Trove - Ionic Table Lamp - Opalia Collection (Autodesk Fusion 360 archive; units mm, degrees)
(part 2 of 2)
create_component "CreateComponent4"
create_component "CreateComponent5"
create_component "CreateComponent6"
create_component "CreateComponent7"
create_component "CreateComponent8"
remove_body "RemoveBody1"
create_component "CreateComponent9"
create_component "CreateComponent10"
create_component "CreateComponent11"
create_component "CreateComponent12"
create_component "CreateComponent13"
create_component "CreateComponent14"
create_component "CreateComponent15"
create_component "CreateComponent16"
create_component "CreateComponent17"
create_component "CreateComponent18"
remove_body "RemoveBody6"
create_component "CreateComponent19"
create_component "CreateComponent20"
create_component "CreateComponent21"
create_component "CreateComponent22"
create_component "CreateComponent23"
named bodies: "Marble Base", "Rotary Switch", "Coiled - SVT (Blk Fabric)", "Glass Globe", "Metal Housing", "Metal Socket Cover", "Porcelain Socket", "Brass Dial - Dimmer Knob", "Solitaire Petite", "Facet Petite", "Body1", "Body2", "Plastic Insert", "Silicone Gasket", "Oculo Petite", "Balon v2", "Balon v3", "Trove - TL", "Trove - TL (1)", "Neoprene Pad", "2-Pole Plug End", "Rubber Grommet", "Chinois"

design "Trove - TL"
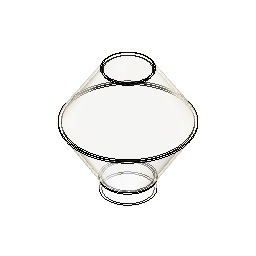
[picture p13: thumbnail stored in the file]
derived_base_feature "Derived Base Feature" bodies "Trove"
hole "Hole1" HoleDepth 88.9 HoleDiameter 44.45 TipAngle 118
sketch "Sketch1" plane through (0, 0, 0) normal (1, 0, 0) x axis (0, 1, 0)
  line L1 (0, 243.0601) -> (0, 247.8226)
  line L2 (-50.8, -12.7122) -> (-50.8, 10.9447)
  line L3 (0, -25.4) -> (0, 243.0601)
  line L4 (-46.0375, -12.7122) -> (-50.8, -12.7122)
  line L5 (-46.0375, -12.7122) -> (-46.0375, 12.3043)
  line L6 (-45.9716, 247.8226) -> (0, 247.8226)
  line L7 (-43.3841, 243.0601) -> (0, 243.0601)
  line L8 (-122.8321, 128.6352) -> (-51.757, 14.2971)
  line L9 (-117.1907, 128.5808) -> (-46.9945, 15.6567)
  line L10 (-48.6353, 246.3754) -> (-122.7993, 132.0392)
  line L11 (-46.0478, 241.6129) -> (-117.1579, 131.9848)
  arc A1 centre (-57.15, 10.9447) radius 6.35 clockwise from (-51.757, 14.2971) to (-50.8, 10.9447)
  arc A2 centre (-52.3875, 12.3043) radius 6.35 clockwise from (-46.9945, 15.6567) to (-46.0375, 12.3043)
  arc A3 centre (-114.4942, 130.257) radius 3.175 between (-117.1579, 131.9848) and (-117.1907, 128.5808)
  arc A4 centre (-120.1356, 130.3114) radius 3.175 between (-122.7993, 132.0392) and (-122.8321, 128.6352)
  arc A5 centre (-45.9716, 244.6476) radius 3.175 between (-45.9716, 247.8226) and (-48.6353, 246.3754)
  arc A6 centre (-43.3841, 239.8851) radius 3.175 clockwise from (-46.0478, 241.6129) to (-43.3841, 243.0601)
  point P3 (0, 247.8226)
  point P4 (0, 243.0601)
  vertical L1
  vertical L3
  tangent L5 A2
  perpendicular L1 L6
  perpendicular L1 L7
  tangent L11 A3
  tangent L9 A3
  tangent L10 A4
  tangent L8 A4
  equal A3 A4
  tangent L6 A5
  tangent L10 A5
  tangent L11 A6
  tangent L7 A6
  dimension "d8" distance P3 P4 = 4.7625
  dimension "d11" radius A2 = 6.35
  dimension "d15" radius A3 = 3.175
  dimension "d16" radius A5 = 3.175
  dimension "d17" radius A6 = 3.175
revolve "Revolve1" sketch "Sketch1" AlongAngle 180 bodies "Trove - TL"
revolve "Revolve2" sketch "Sketch1" AlongAngle -180
component_from_bodies "Body->Comp"
remove_body "RemoveBody2"
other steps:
base_feature "Base Feature" bodies "Trove - TL"
create_component "CreateComponent1"
remove_body "RemoveBody1"
named bodies: "Trove", "Trove - TL"

design "T9-5In"
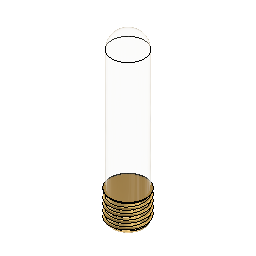
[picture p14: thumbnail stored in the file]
sketch "Sketch1" plane through (0, 0, 0) normal (0, 1, 0) x axis (1, 0, 0)
  line L1 (0, 0) -> (0, -127)
  line L2 (12.7, -127) -> (-12.7, -127)
  line L3 (12.7, -12.7) -> (12.7, -127)
  line L4 (-12.7, -127) -> (-12.7, -12.7)
  arc A1 centre (0, -12.7) radius 12.7 clockwise from (-12.7, -12.7) to (12.7, -12.7)
  point P1 (0, 0)
  point P3 (0, 0)
  coincident P1 P3
  vertical L1
  horizontal L2
  vertical L3
  vertical L4
revolve "Revolve1" sketch "Sketch1" AlongAngle 360 bodies "BU-T10-5-LED-120V"
derived_base_feature "Derived Base Feature" bodies "E26 Base"
move "Move1"
component_from_bodies "Body->Comp"
copy_paste "CutPaste"
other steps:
base_feature "Base Feature" bodies "BU-T10-5-LED-120V"
create_component "CreateComponent1"
create_component "CreateComponent2"
remove_body "RemoveBody1"
remove_instance "RemoveInstance1"
named bodies: "BU-T10-5-LED-120V", "E26 Base"

design "Balon v2"
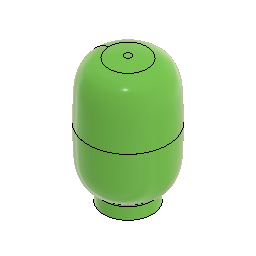
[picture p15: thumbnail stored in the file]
derived_base_feature "Derived Base Feature" bodies "Balon"
work_plane "WorkPlane1" AlongDistance 0
sketch "Sketch1" plane through (0, 0, 0) normal (0, 1, 0) x axis (1, 0, 0)
  line L1 (0, 317.5) -> (0, 2.9083)
  curve K1 (-82.9821, 124.2212) -> (-50.8, 237.8015)
  curve K2 (-51.0925, 237.681) -> (-50.8, 237.8015)
  curve K3 (-51.3855, 237.5558) -> (-51.0925, 237.681)
  curve K4 (-54.7608, 236.0513) -> (-51.3855, 237.5558)
  curve K5 (-57.9615, 234.05) -> (-54.7608, 236.0513)
  curve K6 (-67.2727, 226.749) -> (-57.9615, 234.05)
  curve K7 (-69.0552, 224.2615) -> (-67.2727, 226.749)
  curve K8 (-72.1872, 218.7832) -> (-69.0552, 224.2615)
  curve K9 (-74.1213, 215.1556) -> (-72.1872, 218.7832)
  curve K10 (-78.3031, 204.3965) -> (-74.1213, 215.1556)
  curve K11 (-79.7275, 197.3397) -> (-78.3031, 204.3965)
  curve K12 (-81.3333, 185.4664) -> (-79.7275, 197.3397)
  curve K13 (-81.6254, 178.4008) -> (-81.3333, 185.4664)
  curve K14 (-82.49, 152.2133) -> (-81.6254, 178.4008)
  curve K15 (-82.9821, 136.067) -> (-82.49, 152.2133)
  curve K16 (-82.9821, 124.2212) -> (-82.9821, 136.067)
  curve K17 (50.8, 237.7999) -> (82.9821, 124.2212)
  curve K18 (82.9821, 140.3031) -> (82.9821, 124.2212)
  curve K19 (81.9353, 169.4257) -> (82.9821, 140.3031)
  curve K20 (81.3621, 183.6489) -> (81.9353, 169.4257)
  curve K21 (80.9478, 189.8724) -> (81.3621, 183.6489)
  curve K22 (77.8147, 206.9858) -> (80.9478, 189.8724)
  curve K23 (74.9652, 213.2153) -> (77.8147, 206.9858)
  curve K24 (69.4688, 224.1531) -> (74.9652, 213.2153)
  curve K25 (67.2512, 226.458) -> (69.4688, 224.1531)
  curve K26 (61.5696, 231.3138) -> (67.2512, 226.458)
  curve K27 (57.377, 234.6711) -> (61.5696, 231.3138)
  curve K28 (52.0556, 237.2628) -> (57.377, 234.6711)
  curve K29 (51.4313, 237.5413) -> (52.0556, 237.2628)
  curve K30 (50.8, 237.7999) -> (51.4313, 237.5413)
  line L2 (-50.8, 317.5) -> (-50.8, 237.8015)
  line L3 (50.8, 317.5) -> (50.8, 237.7999)
  line L4 (-19.0713, 6.7501) -> (-19.0713, 6.7501)
  curve K31 (82.9821, 124.1958) -> (40.1509, 7.3012)
  curve K32 (41.8198, 7.6176) -> (40.1509, 7.3012)
  curve K33 (43.2113, 8.0663) -> (41.8198, 7.6176)
  curve K34 (47.0139, 9.2854) -> (43.2113, 8.0663)
  curve K35 (47.3314, 9.3805) -> (47.0139, 9.2854)
  curve K36 (50.1192, 10.3272) -> (47.3314, 9.3805)
  curve K37 (51.833, 11.0085) -> (50.1192, 10.3272)
  curve K38 (57.8313, 14.1895) -> (51.833, 11.0085)
  curve K39 (61.4491, 17.0488) -> (57.8313, 14.1895)
  curve K40 (66.8203, 21.5867) -> (61.4491, 17.0488)
  curve K41 (68.5372, 23.5528) -> (66.8203, 21.5867)
  curve K42 (71.2201, 27.8971) -> (68.5372, 23.5528)
  curve K43 (74.7424, 33.8984) -> (71.2201, 27.8971)
  curve K44 (78.2342, 44.8406) -> (74.7424, 33.8984)
  curve K45 (79.6792, 50.3463) -> (78.2342, 44.8406)
  curve K46 (81.3558, 63.5576) -> (79.6792, 50.3463)
  curve K47 (81.6386, 70.4415) -> (81.3558, 63.5576)
  curve K48 (82.4897, 96.2198) -> (81.6386, 70.4415)
  curve K49 (82.9814, 112.3523) -> (82.4897, 96.2198)
  curve K50 (82.9821, 124.1958) -> (82.9814, 112.3523)
  curve K51 (-40.1501, 7.301) -> (-82.9821, 124.1958)
  curve K52 (-82.9813, 110.5256) -> (-82.9821, 124.1958)
  curve K53 (-82.2545, 88.8594) -> (-82.9813, 110.5256)
  curve K54 (-81.6277, 70.519) -> (-82.2545, 88.8594)
  curve K55 (-81.3572, 64.3441) -> (-81.6277, 70.519)
  curve K56 (-79.4149, 46.8924) -> (-81.3572, 64.3441)
  curve K57 (-76.5204, 38.9768) -> (-79.4149, 46.8924)
  curve K58 (-73.5142, 32.2947) -> (-76.5204, 38.9768)
  curve K59 (-72.5556, 30.3818) -> (-73.5142, 32.2947)
  curve K60 (-69.7914, 25.3691) -> (-72.5556, 30.3818)
  curve K61 (-68.3824, 23.4028) -> (-69.7914, 25.3691)
  curve K62 (-64.5419, 19.5456) -> (-68.3824, 23.4028)
  curve K63 (-62.3002, 17.7646) -> (-64.5419, 19.5456)
  curve K64 (-53.6583, 11.1976) -> (-62.3002, 17.7646)
  curve K65 (-49.6968, 10.1396) -> (-53.6583, 11.1976)
  curve K66 (-43.4141, 8.1331) -> (-49.6968, 10.1396)
  curve K67 (-41.9704, 7.6516) -> (-43.4141, 8.1331)
  curve K68 (-40.1963, 7.3098) -> (-41.9704, 7.6516)
  curve K69 (-40.1732, 7.3054) -> (-40.1963, 7.3098)
  curve K70 (-40.1501, 7.301) -> (-40.1732, 7.3054)
  line L5 (-82.9821, 124.1958) -> (-82.9821, 124.2212)
  line L6 (82.9821, 124.2212) -> (82.9821, 124.1958)
  line L7 (0, 317.5) -> (-50.8, 317.5)
  line L8 (7.2015, 3.048) -> (0, 3.048)
  line L9 (0, 3.048) -> (-7.2015, 3.048)
  arc A1 centre (0, 188.595) radius 185.6867 clockwise from (-7.2015, 3.048) to (-40.1502, 7.301)
  arc A2 centre (0, 188.595) radius 185.6867 clockwise from (40.151, 7.3012) to (7.2015, 3.048)
  point P38 (-40.1502, 7.301)
  point P43 (40.1509, 7.3012)
  point P62 (-40.1501, 7.301)
  point P81 (40.151, 7.3012)
  point P84 (0, 3.048)
  vertical L1
  horizontal L4
  coincident P38 K51
  symmetric L1 A1 A2
  coincident A2 P43
  coincident A1 P62
  coincident K31 P81
  perpendicular L2 L7
  horizontal L8
  coincident L1 P84
  horizontal L9
revolve "Revolve1" sketch "Sketch1" AlongAngle 360
shell "Shell1" innerThickness 3.81
fillet "Fillet1" radius 6.35
offset_faces "OffsetFaces1" distance -50.8
move "Move1"
move "Move2"
component_from_bodies "Body->Comp1"
component_from_bodies "Body->Comp2"
sketch "Sketch2" plane through (0, 0, 0) normal (0, 1, 0) x axis (1, 0, 0)
  line L1 (-85.5221, 124.2212) -> (-85.5221, 124.1961)
  curve K1 (-58.9057, 236.4383) -> (-50.8, 241.7989)
  curve K2 (-50.8, 241.554) -> (-50.8, 241.7989)
  curve K3 (-50.904, 240.933) -> (-50.8, 241.554)
  curve K4 (-51.2936, 240.2837) -> (-50.904, 240.933)
  curve K5 (-51.734, 239.7561) -> (-51.2936, 240.2837)
  curve K6 (-53.328, 238.5038) -> (-51.734, 239.7561)
  curve K7 (-54.0892, 238.1997) -> (-53.328, 238.5038)
  curve K8 (-58.9057, 236.4383) -> (-54.0892, 238.1997)
  curve K9 (-89.3309, 124.2212) -> (-58.9057, 236.4383)
  curve K10 (-62.6336, 234.9735) -> (-58.9057, 236.4383)
  curve K11 (-65.581, 233.1032) -> (-62.6336, 234.9735)
  curve K12 (-73.0224, 227.0019) -> (-65.581, 233.1032)
  curve K13 (-74.8981, 224.836) -> (-73.0224, 227.0019)
  curve K14 (-78.1104, 219.6097) -> (-74.8981, 224.836)
  curve K15 (-80.2663, 215.561) -> (-78.1104, 219.6097)
  curve K16 (-84.0943, 205.8277) -> (-80.2663, 215.561)
  curve K17 (-85.4655, 200.1154) -> (-84.0943, 205.8277)
  curve K18 (-87.4092, 188.5789) -> (-85.4655, 200.1154)
  curve K19 (-87.7349, 182.3889) -> (-87.4092, 188.5789)
  curve K20 (-88.4233, 165.9645) -> (-87.7349, 182.3889)
  curve K21 (-89.328, 138.6964) -> (-88.4233, 165.9645)
  curve K22 (-89.3309, 124.2212) -> (-89.328, 138.6964)
  line L2 (-89.3309, 124.1958) -> (-89.3309, 124.2212)
  curve K23 (-46.5001, 7.301) -> (-89.3309, 124.1958)
  curve K24 (-89.3314, 112.4293) -> (-89.3309, 124.1958)
  curve K25 (-88.8181, 95.3068) -> (-89.3314, 112.4293)
  curve K26 (-88.346, 81.2892) -> (-88.8181, 95.3068)
  curve K27 (-88.0298, 70.4902) -> (-88.346, 81.2892)
  curve K28 (-87.1514, 58.328) -> (-88.0298, 70.4902)
  curve K29 (-86.3326, 50.6119) -> (-87.1514, 58.328)
  curve K30 (-81.0932, 33.6688) -> (-86.3326, 50.6119)
  curve K31 (-77.3163, 27.4309) -> (-81.0932, 33.6688)
  curve K32 (-74.8955, 23.6666) -> (-77.3163, 27.4309)
  curve K33 (-73.5108, 22.0741) -> (-74.8955, 23.6666)
  curve K34 (-70.2346, 19.0457) -> (-73.5108, 22.0741)
  curve K35 (-64.8094, 14.3548) -> (-70.2346, 19.0457)
  curve K36 (-56.6696, 10.3041) -> (-64.8094, 14.3548)
  curve K37 (-54.0053, 9.483) -> (-56.6696, 10.3041)
  curve K38 (-49.1487, 7.9411) -> (-54.0053, 9.483)
  curve K39 (-48.3482, 7.6526) -> (-49.1487, 7.9411)
  curve K40 (-46.5001, 7.301) -> (-48.3482, 7.6526)
  line L3 (0, 266.7) -> (0, 0)
  line L4 (0, 3.048) -> (-7.7894, 3.048)
  line L5 (-50.8, 266.7) -> (-50.8, 241.7989)
  line L6 (0, 266.7) -> (-50.8, 266.7)
  arc A1 centre (-6.9779, 188.7329) radius 185.6867 clockwise from (-7.7894, 3.048) to (-46.5001, 7.301)
  point P1 (0, 0)
  point P44 (0, 0)
  point P46 (0, 3.048)
  point P5 (-50.8, 241.554)
  point P49 (0, 266.7)
  coincident P1 P44
  coincident L3 P46
  coincident P5 L5
  coincident L3 P49
revolve "Revolve2" sketch "Sketch2" AlongAngle 360 bodies "Balon v3"
shell "Shell2" innerThickness 3.81
component_from_bodies "Body->Comp3"
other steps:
base_feature "Base Feature1" bodies "Balon"
base_feature "Base Feature1" bodies "Balon v3"
base_feature "Base Feature1" bodies "Balon v2"
create_component "CreateComponent1"
remove_body "RemoveBody1"
create_component "CreateComponent2"
remove_body "RemoveBody2"
create_component "CreateComponent3"
remove_body "RemoveBody3"
named bodies: "Balon", "Balon v2", "Balon v3"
